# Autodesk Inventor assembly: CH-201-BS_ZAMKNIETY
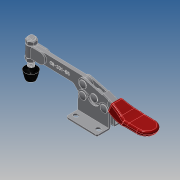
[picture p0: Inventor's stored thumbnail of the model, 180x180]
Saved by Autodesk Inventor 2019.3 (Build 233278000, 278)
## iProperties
Company: ·L?¤¤?
Created: 2010-06
Part Number: CH-201-BS_ZAMKNIETY
Material: Ogólny
Description: STEP AP203
Document SubType Name: Assembly
Designer: CADENGINEERING4
Title: CH-201-BS.STEP
Author: ·L?¥Î?
Revision Number: ANY
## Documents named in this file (9)
- E:\STRONA\Horizontal toggle clamp\CH-201-BS\CH-201-BS_ZAMKNIETY.iam
- E:\STRONA\Horizontal toggle clamp\CH-201-BS\14134-02___.ipt
- E:\STRONA\Horizontal toggle clamp\CH-201-BS\201-B-04___.ipt
- E:\STRONA\Horizontal toggle clamp\CH-201-BS\201-BS-02___.ipt
- E:\STRONA\Horizontal toggle clamp\CH-201-BS\201-B-06___.ipt
- E:\STRONA\Horizontal toggle clamp\CH-201-BS\14134___.ipt
- E:\STRONA\Horizontal toggle clamp\CH-201-BS\BR-142___.ipt
- E:\STRONA\Horizontal toggle clamp\CH-201-BS\201-B___.iam
- E:\STRONA\Horizontal toggle clamp\CH-201-BS\201-B-01___.ipt
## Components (13 placed, 13 different names)
1. 14134-02_??_1 — Równoległe:1, Zestawiające:4, Zestawiające:5
2. 201-B-04_??_2 — Zestawiające:8, Zestawiające:9, Zestawiające:10
3. 201-BS-02_??_3 — Zestawiające:1, Zestawiające:2, Równoległe:2, Zestawiające:19, Zestawiające:22, Zestawiające:23, Zestawiające:24, Zestawiające:25
4. 201-B-06_??_4 — Zestawiające:13, Zestawiające:14
5. 201-B-06_??_5 — Zestawiające:20, Zestawiające:21, Zestawiające:23
6. 14134_??_6 — Równoległe:1, Zestawiające:3, Zestawiające:4, Zestawiające:7
7. 201-B-04_??_7 — Zestawiające:8, Zestawiające:9, Zestawiające:10, Zestawiające:11, Zestawiające:12, Zestawiające:15, Zestawiające:16
8. 14134-02_??_8 — Zestawiające:3, Zestawiające:6
9. BR-142_??_9 — Zestawiające:1, Zestawiające:2, Równoległe:2, Zestawiające:5, Zestawiające:6, Zestawiające:7
10. 201-B_??_10 [sub-assembly] — Zestawiające:15, Zestawiające:16, Zestawiające:17, Zestawiające:18, Zestawiające:19, Zestawiające:20, Zestawiające:21, Zestawiające:22, Przejściowe:1
11. 201-B-06_??_11 — Zestawiające:17, Zestawiające:18
12. 201-B-01_??_12 — Zestawiające:11, Zestawiające:12, Zestawiające:13, Zestawiające:14, Zestawiające:24, Zestawiające:26, Przejściowe:1
13. 201-B-06_??_13 — Zestawiające:25, Zestawiające:26
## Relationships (29: Mate 26, Flush 2, Transitional 1)
- Równoległe:1 [Flush]: 14134-02_??_1 ↔ 14134_??_6
- Zestawiające:1 [Mate]: 201-BS-02_??_3 ↔ BR-142_??_9
- Zestawiające:2 [Mate]: 201-BS-02_??_3 ↔ BR-142_??_9
- Równoległe:2 [Flush]: 201-BS-02_??_3 ↔ BR-142_??_9
- Zestawiające:3 [Mate]: 14134_??_6 ↔ 14134-02_??_8
- Zestawiające:4 [Mate]: 14134-02_??_1 ↔ 14134_??_6
- Zestawiające:5 [Mate]: 14134-02_??_1 ↔ BR-142_??_9
- Zestawiające:6 [Mate]: 14134-02_??_8 ↔ BR-142_??_9
- Zestawiające:7 [Mate]: 14134_??_6 ↔ BR-142_??_9
- Zestawiające:8 [Mate]: 201-B-04_??_2 ↔ 201-B-04_??_7
- Zestawiające:9 [Mate]: 201-B-04_??_2 ↔ 201-B-04_??_7
- Zestawiające:10 [Mate]: 201-B-04_??_2 ↔ 201-B-04_??_7
- Zestawiające:11 [Mate]: 201-B-04_??_7 ↔ 201-B-01_??_12
- Zestawiające:12 [Mate]: 201-B-04_??_7 ↔ 201-B-01_??_12
- Zestawiające:13 [Mate]: 201-B-06_??_4 ↔ 201-B-01_??_12
- Zestawiające:14 [Mate]: 201-B-06_??_4 ↔ 201-B-01_??_12
- Zestawiające:15 [Mate]: 201-B-04_??_7 ↔ 201-B_??_10
- Zestawiające:16 [Mate]: 201-B-04_??_7 ↔ 201-B_??_10
- Zestawiające:17 [Mate]: 201-B_??_10 ↔ 201-B-06_??_11
- Zestawiające:18 [Mate]: 201-B_??_10 ↔ 201-B-06_??_11
- Zestawiające:19 [Mate]: 201-BS-02_??_3 ↔ 201-B_??_10
- Zestawiające:20 [Mate]: 201-B-06_??_5 ↔ 201-B_??_10
- Zestawiające:21 [Mate]: 201-B-06_??_5 ↔ 201-B_??_10
- Zestawiające:22 [Mate]: 201-BS-02_??_3 ↔ 201-B_??_10
- Zestawiające:23 [Mate]: 201-BS-02_??_3 ↔ 201-B-06_??_5
- Zestawiające:24 [Mate]: 201-BS-02_??_3 ↔ 201-B-01_??_12
- Zestawiające:25 [Mate]: 201-BS-02_??_3 ↔ 201-B-06_??_13
- Zestawiające:26 [Mate]: 201-B-01_??_12 ↔ 201-B-06_??_13
- Przejściowe:1 [Transitional]: 201-B_??_10 ↔ 201-B-01_??_12
